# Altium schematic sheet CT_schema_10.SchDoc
size 278 x 170 mm
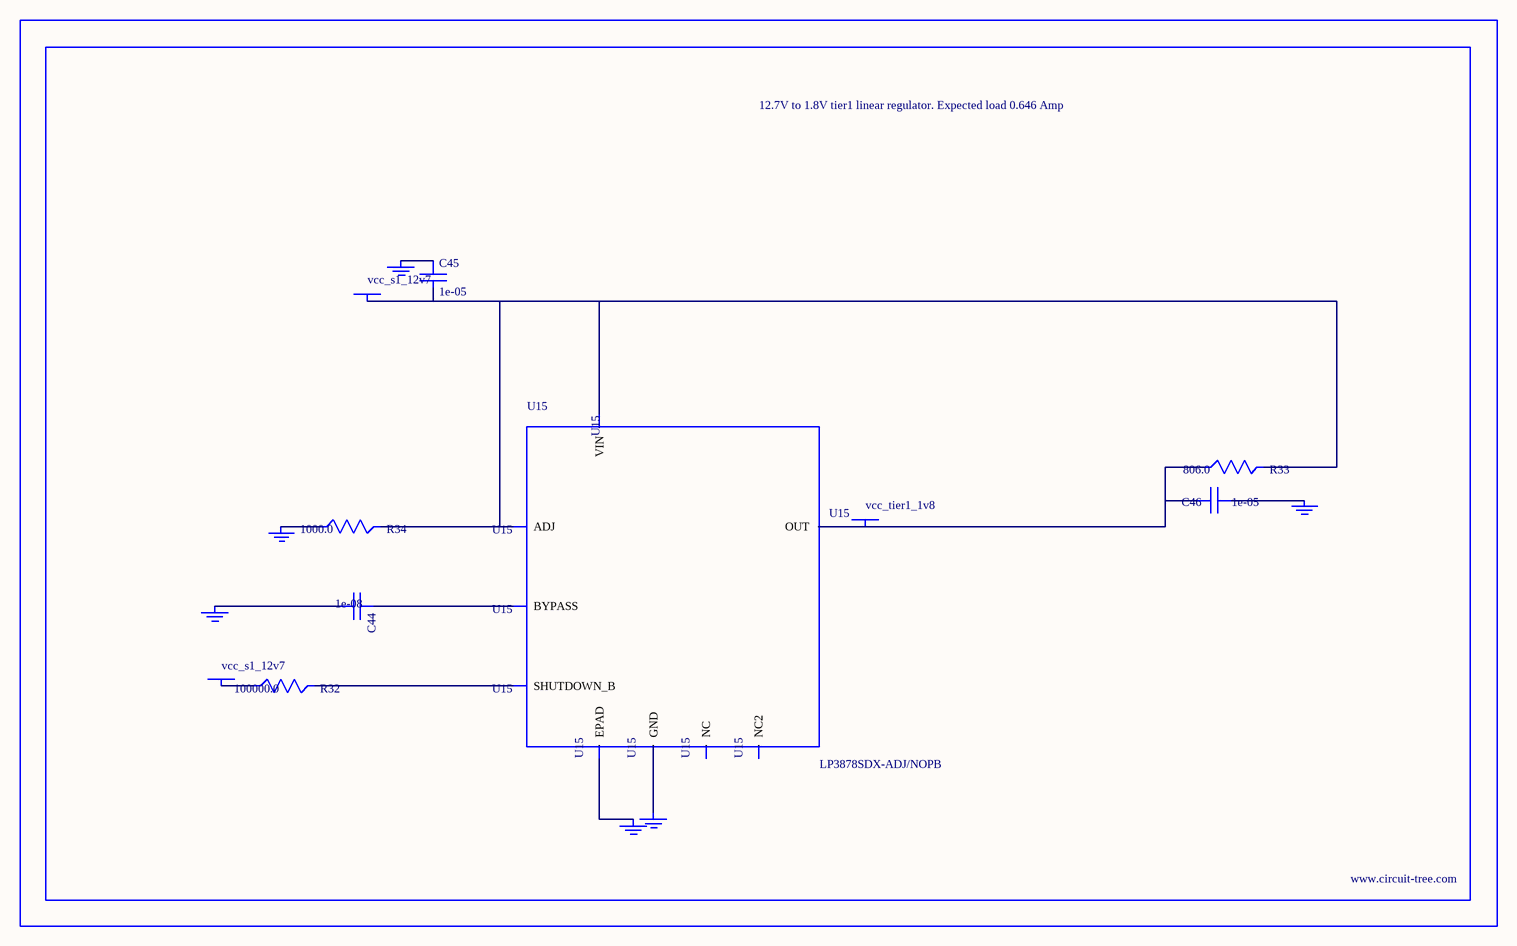
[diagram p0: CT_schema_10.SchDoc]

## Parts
BORDER9  (no value)
C44  1e-08  [C0402]
C45  1e-05  [C1210]
C46  1e-05  [C0805]
GND_INSTANCE_9_0  (no value)
GND_INSTANCE_9_1  (no value)
GND_INSTANCE_9_2  (no value)
GND_INSTANCE_9_3  (no value)
GND_INSTANCE_9_4  (no value)
GND_INSTANCE_9_5  (no value)
POWER_INSTANCE_9_0  vcc_s1_12v7
POWER_INSTANCE_9_1  vcc_s1_12v7
POWER_INSTANCE_9_2  vcc_tier1_1v8
R32  100000.0  [R0603]
R33  806.0  [R0603]
R34  1000.0  [R0603]
U15  LP3878SDX-ADJ/NOPB  [WSON-8]

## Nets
NetC44_1: C44.1 U15.1(BYPASS)
NetC44_2: C44.2 GND_INSTANCE_9_0.0(GND)
NetC45_1: C45.1 GND_INSTANCE_9_1.0(GND)
NetC45_2: C45.2 POWER_INSTANCE_9_0.0(PWR) R33.2 R34.2 U15.4(VIN) U15.6(ADJ)
NetC46_1: C46.1 GND_INSTANCE_9_2.0(GND)
NetC46_2: C46.2 POWER_INSTANCE_9_2.0(PWR) R33.1 U15.5(OUT)
NetGND_INSTANCE_9_3_0: GND_INSTANCE_9_3.0(GND) R34.1
NetGND_INSTANCE_9_4_0: GND_INSTANCE_9_4.0(GND) U15.PAD(EPAD)
NetGND_INSTANCE_9_5_0: GND_INSTANCE_9_5.0(GND) U15.3(GND)
NetPOWER_INSTANCE_9_1_0: POWER_INSTANCE_9_1.0(PWR) R32.1
NetR32_2: R32.2 U15.8(SHUTDOWN_B)

Not connected (* = marked no-connect by the designer): U15 2(NC) 7(NC2)

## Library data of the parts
BORDER9 = BORDER_PAGE9
C44 = C0402C103K3RAC
C45 = C1210C106K5PACTU
C46 = GRM219R60J106ME19D
GND_INSTANCE_9_0-GND_INSTANCE_9_5 = GND
POWER_INSTANCE_9_0-POWER_INSTANCE_9_2 = PWR
R32 = RC0603JR-07100KL
R33 = ERJ-3EKF8060V
R34 = RC0603JR-071KL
